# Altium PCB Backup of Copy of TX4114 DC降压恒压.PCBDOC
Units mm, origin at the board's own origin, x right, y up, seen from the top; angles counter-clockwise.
Board outline 84.26 x 72.93 mm, 3 copper layers (TopLayer, MidLayer5, BottomLayer); 15 components, 21 nets, 57 pads, 0 vias.
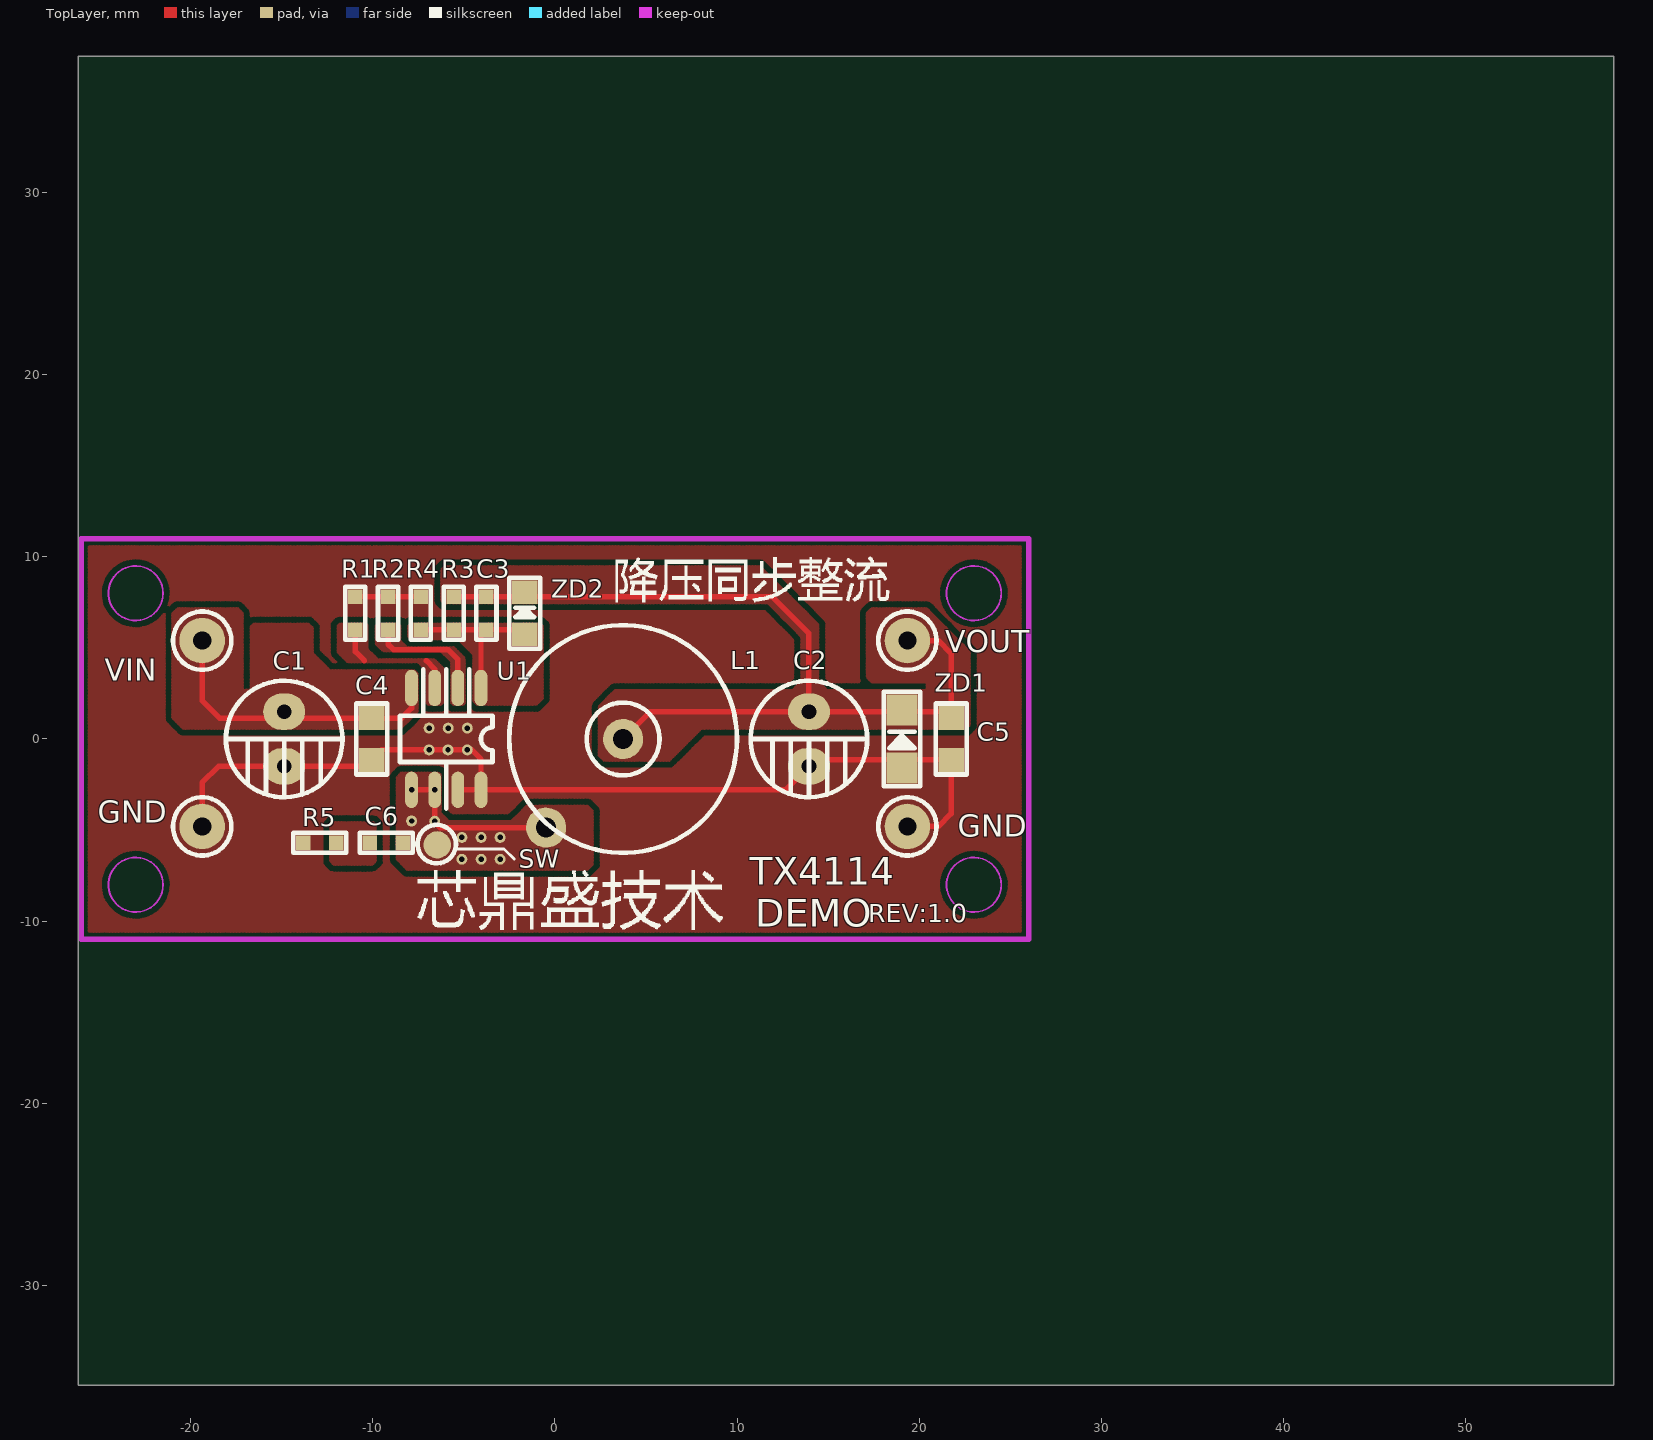
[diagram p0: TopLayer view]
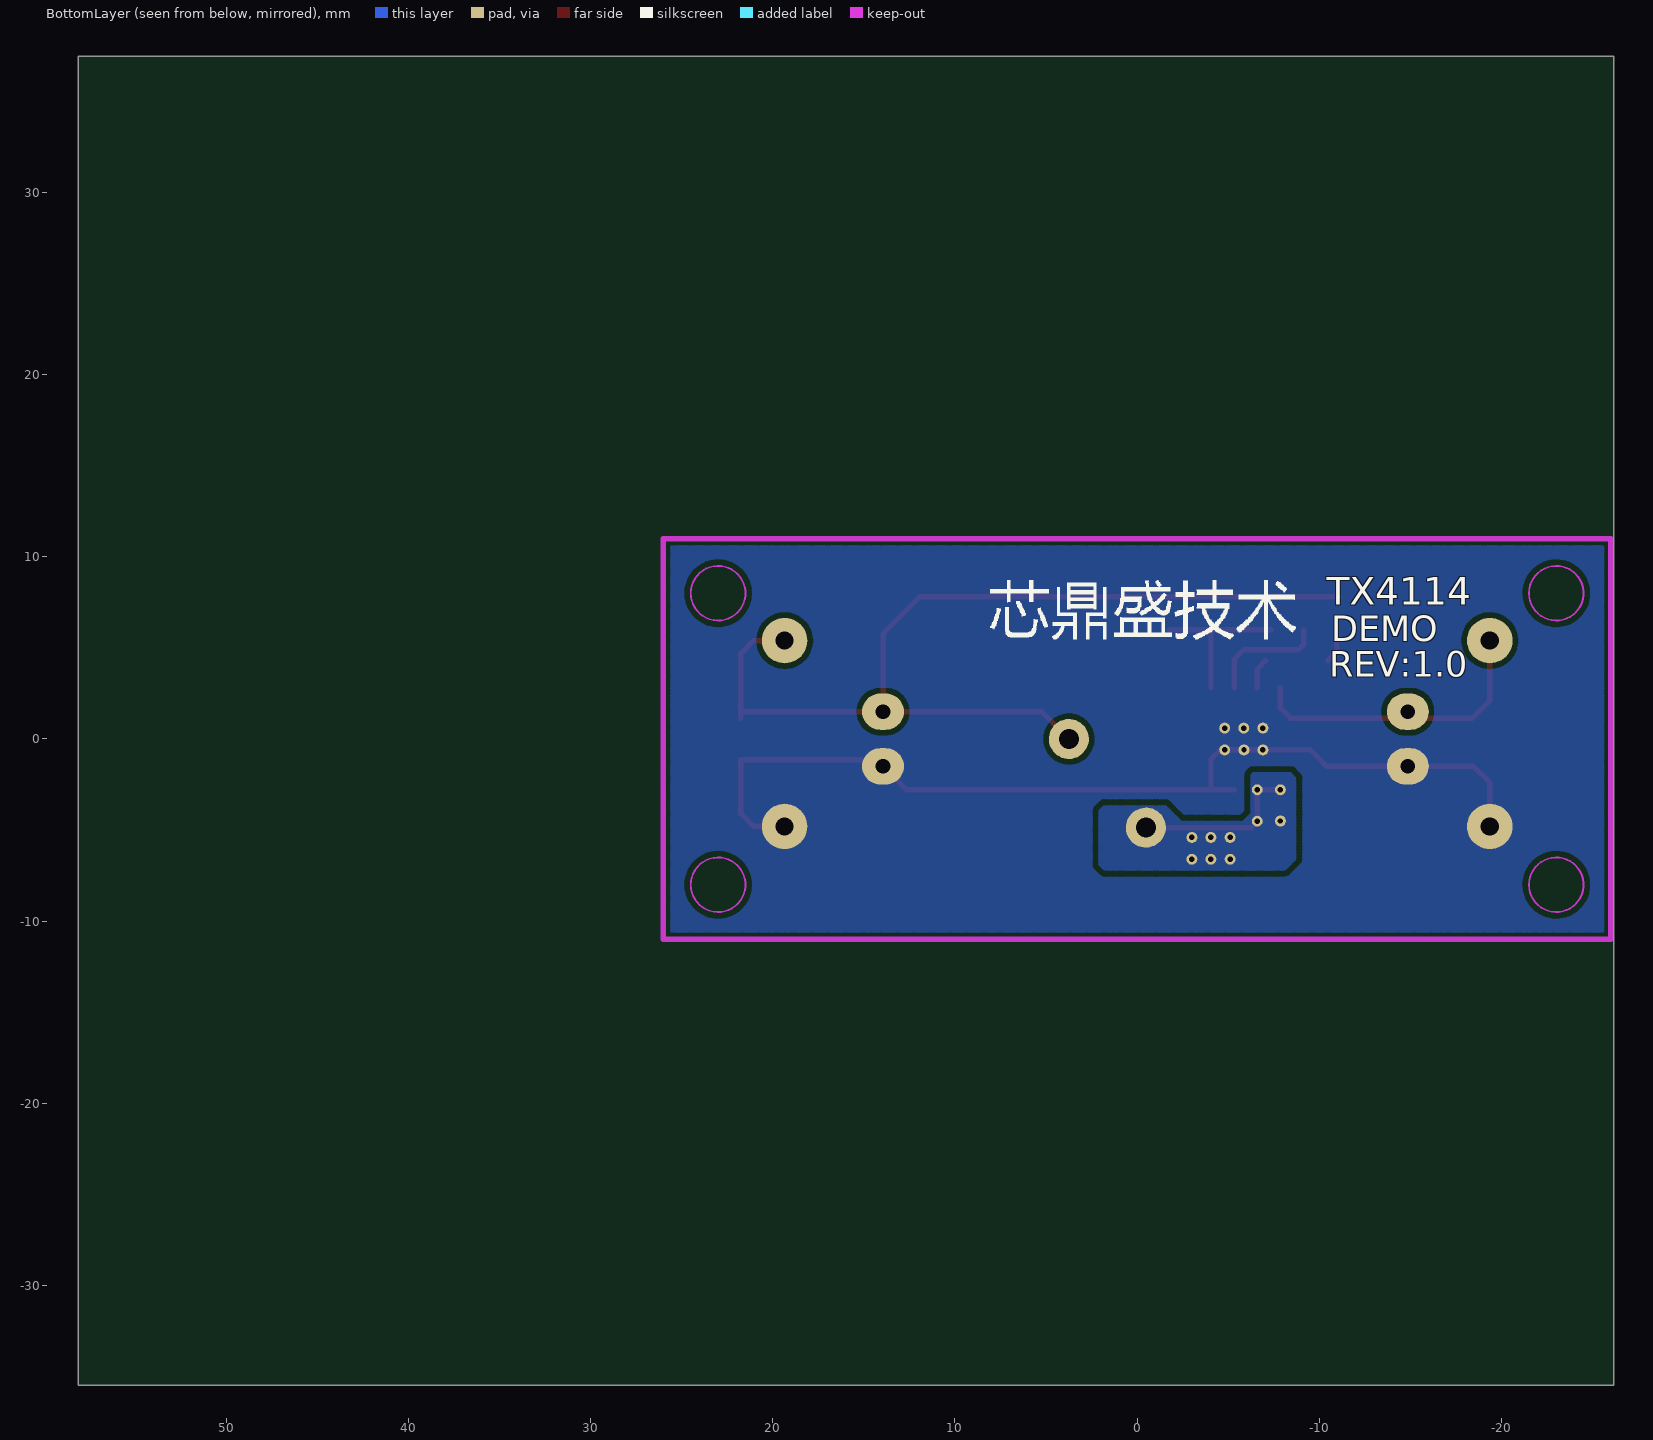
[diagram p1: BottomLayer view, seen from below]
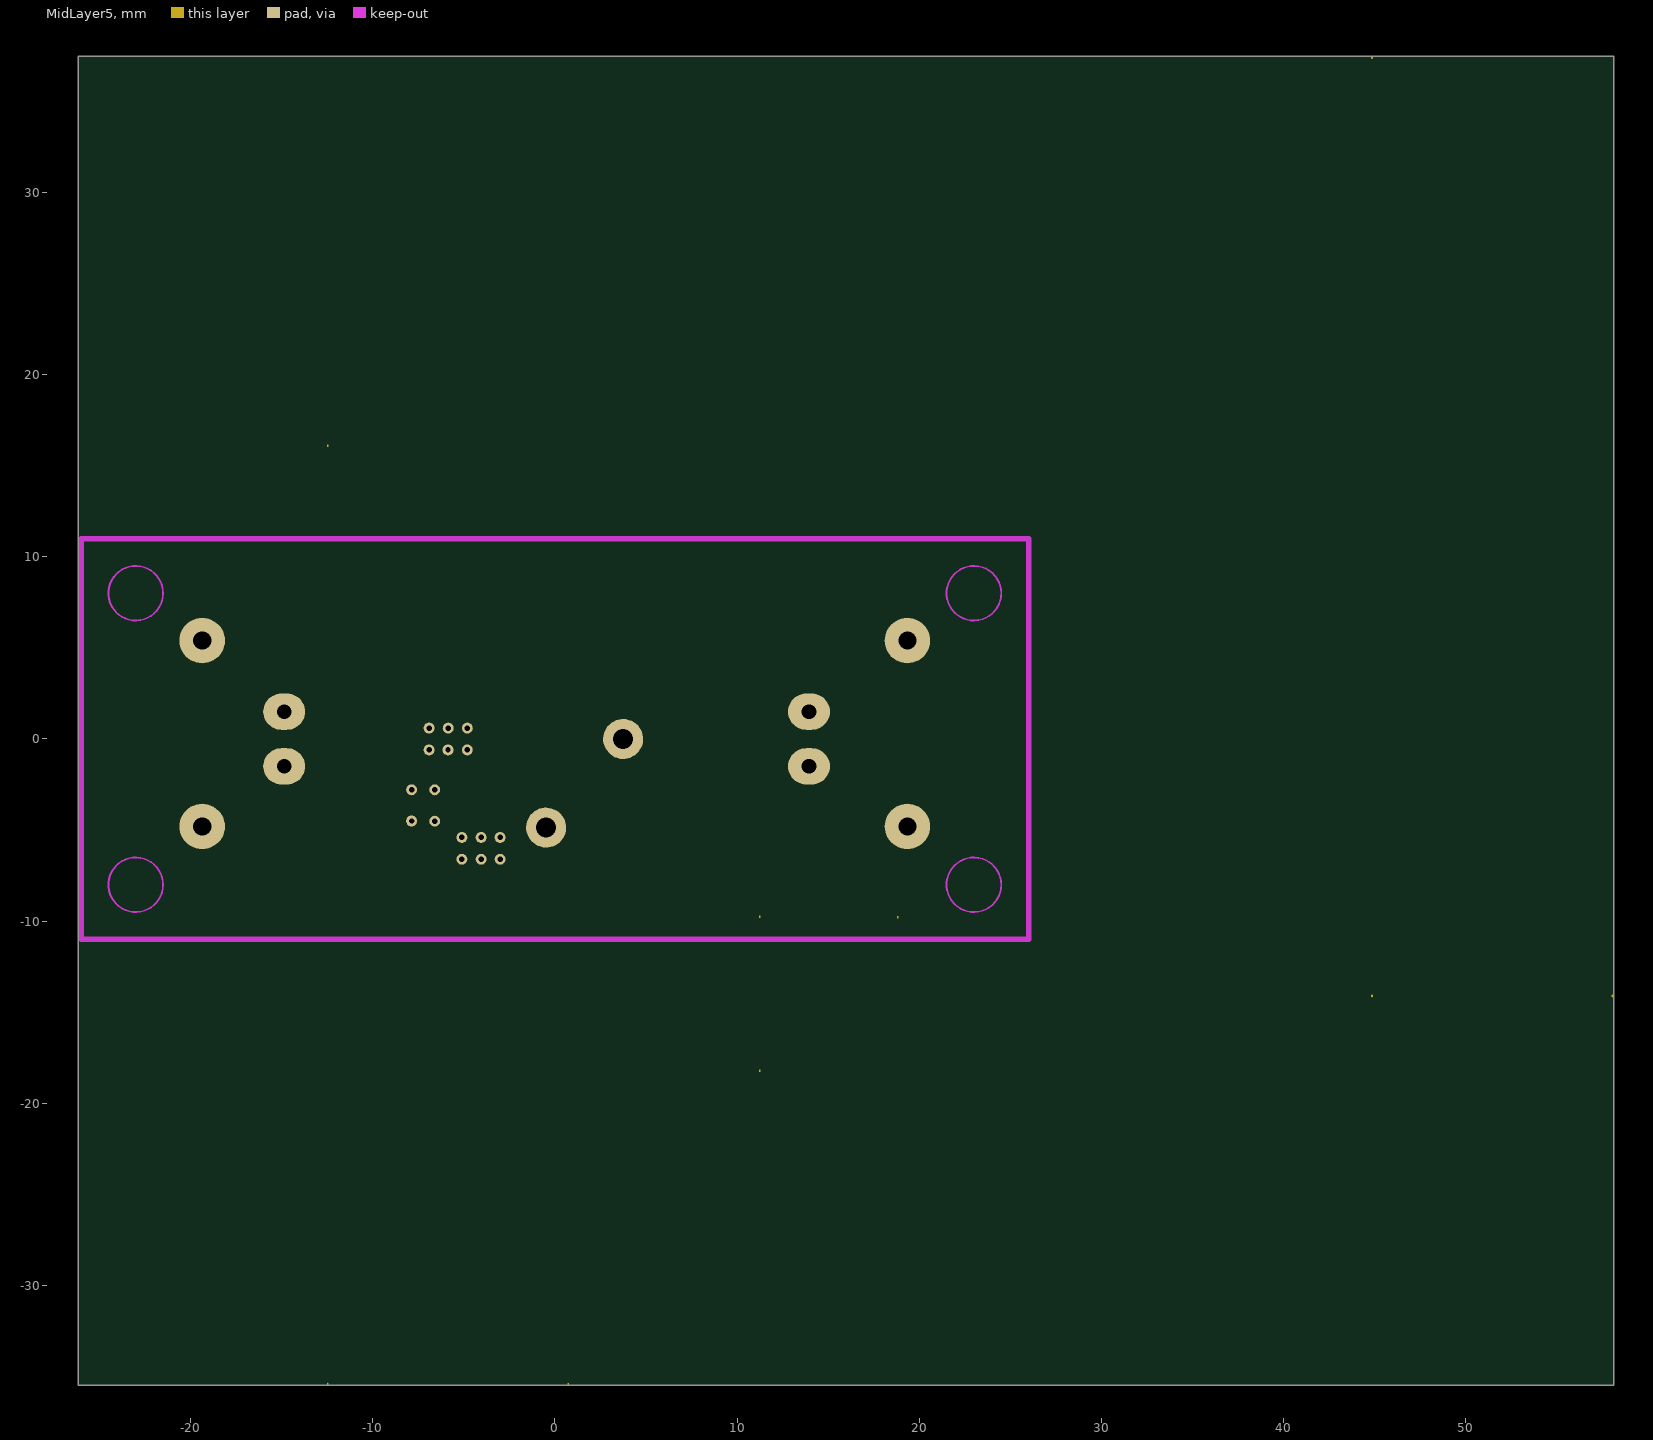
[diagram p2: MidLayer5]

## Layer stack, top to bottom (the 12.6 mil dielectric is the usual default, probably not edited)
TopLayer: signal copper 0.0356
Dielectric: dielectric 0.32, FR-4, Dk 4.8
MidLayer5: signal copper 0.0356
Dielectric: dielectric 0.32, FR-4, Dk 4.8
BottomLayer: signal copper 0.0356

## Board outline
-26.15,-35.464 58.113,-35.464 58.113,37.467 -26.15,37.467

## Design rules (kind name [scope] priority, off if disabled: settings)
Clearance [All] p1: gap=0.3
PlaneConnect [All] p1: planeconnectstyle=Direct reliefexpansion=0.508 reliefentries=4 reliefconductorwidth=0.254 reliefairgap=0.254
PolygonConnect [All] p1: connectstyle=Direct reliefconductorwidth=0.254 reliefentries=4 polygonreliefangle="90 Angle"
RoutingLayers [All] p1: top layer_v5=TRUE mid layer 5_v5=FALSE bottom layer_v5=TRUE
RoutingVias [All] p1: holewidth=0.711 width=1.27 viastyle="Through Hole" minholewidth=0.711 minwidth=1.27 maxholewidth=0.711 maxwidth=1.27
SilkscreenOverComponentPads [All] p1: minsilkscreentomaskgap=0.254
SolderMaskExpansion [All] p1: expansion=0.102
TestPointUsage [All] p1: valid=0 allowmultiple=FALSE
Testpoint [All] p1: side=15 testpointundercomponent=TRUE minsize=1.016 maxsize=2.54 preferedsize=1.524 minholesize=0.508 maxholesize=1.016 preferedholesize=0.813 testpointgrid=0.025 style=1023 order=0123456789
Width [All] p1: maxlimit=0.3 minlimit=0.3 preferedwidth=0.3
21 further rules are at their usual default settings.

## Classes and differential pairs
component class HX1304B: C1 C3 C4 C6 F1 L1 R1 R2 R3 U1

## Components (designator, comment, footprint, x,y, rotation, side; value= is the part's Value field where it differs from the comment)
C1 "100UF/35V" RB-5 -14.85,0 r270 top
C2 "470UF/10V" RB-5 13.95,0 r270 top
C3 "200PF" 0603 -3.75,6.9 r270 top
C4 "104" 0805 -10.05,0 r270 top
C5 "104" 0805 21.75,0 r270 top
C6 "472" 0603 -9.25,-5.7 r0 top
L1 "47UH  44125" L47UH/11.2 3.75,0 r358 top
R1 "68K" 0603 -10.95,6.9 r270 top
R2 "150K" 0603 -9.15,6.9 r270 top
R3 "220K" 0603 -5.55,6.9 r90 top
R4 "68K" 0603 -7.35,6.9 r90 top
R5 "10R" 0603 -12.9,-5.7 r180 top
U1 "TX4114" SO-8 -4.05,2.8 r270 top
ZD1 "6V8" 1206D 19.05,0 r90 top
ZD2 "6V2" 0805D -1.65,6.9 r90 top

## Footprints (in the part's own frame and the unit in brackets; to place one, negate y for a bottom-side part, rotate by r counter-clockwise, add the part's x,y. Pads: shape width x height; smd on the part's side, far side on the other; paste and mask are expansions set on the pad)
0603 [mm]
  rect 0.8x0.8 smd: 1(-0.9,0) 2(0.9,0)
  silkscreen extent -1.45,-0.55 1.45,0.55
0805 [mm]
  rect 1.3x1.4 smd: 1(-1.15,0) 2(1.15,0)
  silkscreen extent -1.95,-0.85 1.95,0.85
0805D [mm]
  rect 1.3x1.4 smd: 1(-1.15,0) 2(1.15,0)
  silkscreen extent -1.95,-0.85 1.95,0.85
1206D [mm]
  rect 1.7x1.7 smd: 1(-1.6,0) 2(1.6,0)
  silkscreen extent -2.6,-1 2.6,1
L47UH/11.2 [mm]
  round 2.2 hole 1.1: 1(-4.051,-5.003) 2(0,0)
  silkscreen extent -6.25,-6.25 6.25,6.25
RB-5 [mm]
  oval 2x2.3 hole 0.8: 1(-1.5,0) 2(1.5,0)
  silkscreen extent -3.2,-3.2 3.2,3.2
SO-8 [mm]
  oval 2x0.7 smd: 1(0,0) 2(0,-1.27) 3(0,-2.54) 4(0,-3.81) 5(5.588,-3.81) 6(5.588,-2.54) 7(5.588,-1.27) 8(5.588,0)
  silkscreen extent -1.03,-4.45 6.61,0.63

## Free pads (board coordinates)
  round 2.5 hole 1: 0(-19.35,5.4) 1(-19.35,-4.8) 2(19.35,5.4) 3(19.35,-4.8)
  round 1.5 smd: 1(-6.45,-5.81)
  round 0.6 hole 0.3: 5(-6.9,0.6) 6(-5.85,0.6) 7(-4.8,0.6) 8(-4.8,-0.6) 9(-5.86,-0.6) 10(-6.9,-0.6) 11(-5.1,-5.4) 12(-4.04,-5.4) 13(-3,-5.4) 14(-5.1,-6.6) 15(-4.04,-6.6) 16(-3,-6.6) 17(-7.86,-2.788) 18(-6.59,-2.788) 19(-7.86,-4.5) 20(-6.59,-4.51)

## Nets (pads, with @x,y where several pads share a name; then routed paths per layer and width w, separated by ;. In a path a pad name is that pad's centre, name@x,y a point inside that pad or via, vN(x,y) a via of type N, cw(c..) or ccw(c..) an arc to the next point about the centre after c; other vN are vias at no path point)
1: C6.1 R5.1
2: 
5: 
6: 
7: 
8: 
EN: 
FB: C3.2 R3.1 R4.1 U1.1 ZD2.1 | length 8.8
  TopLayer w0.3: R4.1 R3.1 C3.2@-4.05,6 ; U1.1 C3.2@-4.05,6 ; ZD2.1@-1.75,6 C3.2 C3.2@-4.05,6
GND: C1.2 C2.2 C4.2 C5.2 pad.1@-19.35,-4.8 pad.3 pad.5 pad.6 pad.7 pad.8 pad.9 pad.10 R1.1 R2.1 R4.2 R5.2 U1.7 U1.8 ZD1.1 | length 57.4
  TopLayer w0.3: pad.1@-19.35,-4.8 -19.35,-2.4 -18.45,-1.5 C1.2 -10.4,-1.5 C4.2 -9.5,-0.6 pad.10 pad.9 pad.8 -4.55,-0.6 -4.05,-1.1 U1.8 ; R1.1@-11.05,7.8 R1.1 R2.1 R4.2 ; U1.7 U1.8 ; pad.3 21.05,-4.8 21.75,-4.1 C5.2 19.05,-1.15 14.3,-1.15 C2.2 12.662,-2.788 U1.8
ILIM: R1.2 U1.3 | length 3.6
  TopLayer w0.3: R1.2 -10.95,4.8 -10.45,4.3 ; -7.05,4.3 -6.59,3.84 U1.3
NetF1_2: 
NetR1_2: 
NetR2_2: 
NetR3_2: 
NetU1_1: 
NetU1_6: 
RT: R2.2 U1.2 | length 6.5
  TopLayer w0.3: R2.2 -9.15,5.2 -8.85,4.9 -5.85,4.9 -5.32,4.37 U1.2
SW: C6.2 L1.1 pad.1@-6.45,-5.81 pad.11 pad.12 pad.13 pad.14 pad.15 pad.16 pad.17 pad.18 pad.19 pad.20 U1.5 U1.6 | length 9.3
  TopLayer w0.3: U1.5 U1.6 pad.20 -6.59,-4.56 -6.292,-4.858 L1.1
VCC: C1.1 C4.1 pad.0 U1.4 | length 16.5
  TopLayer w0.3: pad.0 -19.35,2.1 -18.4,1.15 -14.85,1.15 C4.1 -8.4,1.15 -7.86,1.69 U1.4
VIN: 
VOUT: C2.1 C3.1 C5.1 L1.2 pad.2 R3.2 ZD1.2 ZD2.2 | length 49.3
  TopLayer w0.3: R3.2 11.95,7.8 13.95,5.8 C2.1 ; L1.2 5.25,1.5 C5.1@21.55,1.5 ; pad.2 21.05,5.4 21.75,4.7 C5.1
copper on no net: | length 2.2
  MidLayer5 w0.064: -12.428,-35.4 ccw(c-12.46,-35.4) -12.428,-35.4 ; -12.428,-35.4 ccw(c-12.46,-35.4) -12.428,-35.4 ; 44.882,-14.1 ccw(c44.85,-14.1) 44.882,-14.1 ; 44.882,-14.1 ccw(c44.85,-14.1) 44.882,-14.1 ; -12.428,16.103 ccw(c-12.46,16.103) -12.428,16.103 ; 0.772,-35.4 ccw(c0.74,-35.4) 0.772,-35.4 ; 11.283,-18.209 ccw(c11.251,-18.209) 11.283,-18.209 ; 11.283,-9.747 ccw(c11.251,-9.747) 11.283,-9.747 ; 18.861,-9.782 ccw(c18.829,-9.782) 18.861,-9.782 ; 44.882,37.403 ccw(c44.85,37.403) 44.882,37.403 ; 58.082,-14.1 ccw(c58.05,-14.1) 58.082,-14.1

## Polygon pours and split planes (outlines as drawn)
FB on TopLayer "TopLayer-FB" (hatched 90Degree grid 0.08 track 0.1, remove dead copper, pour order 1000): -4.5,3 -4.5,4.64 -5.31,5.45 -7.88,5.45 -8.05,5.62 -8.05,6.22 -7.92,6.35 -0.78,6.35 -0.64,6.21 -0.64,2.23 -1.02,1.85 -4.25,1.85 -4.5,2.1
RT on TopLayer "TopLayer-RT" (hatched 90Degree grid 0.08 track 0.1, remove dead copper, pour order 1001): -4.92,2.44 -4.92,4.43 -5.53,5.04 -8.1,5.04 -8.45,5.39 -8.45,6.23 -8.57,6.35 -9.71,6.35 -9.84,6.22 -9.84,5.21 -9.43,4.8 -6.26,4.8 -5.7,4.24 -5.7,1.98 -5.57,1.85 -5.02,1.85 -4.92,1.95 -4.92,2.43
ILIM on TopLayer "TopLayer-ILIM" (hatched 90Degree grid 0.08 track 0.1, remove dead copper, pour order 1002): -6.11,2.1 -6.11,3.9 -6.61,4.4 -9.72,4.4 -10.26,4.94 -10.26,6.25 -10.36,6.35 -11.81,6.35 -11.94,6.22 -11.94,4.76 -11.38,4.2 -7.5,4.2 -7.07,3.77 -7.07,1.99 -6.93,1.85 -6.26,1.85 -6.11,2
VCC on TopLayer "TopLayer-VCC" (hatched 90Degree grid 0.08 track 0.1, remove dead copper, pour order 1003): -7.5,3.3 -7.5,1.5 -8.45,0.55 -20.4,0.55 -21,1.15 -21,6.9 -20.7,7.2 -17.4,7.2 -17.1,6.9 -17.1,2.71 -16.7,2.71 -16.7,6.17 -16.52,6.35 -13.5,6.35 -13.26,6.11 -13.26,4.72 -12.34,3.8 -7.71,3.8 -7.5,3.59
SW on TopLayer "TopLayer-SW" (hatched 90Degree grid 0.08 track 0.1, remove dead copper, pour order 1004): -6.24,-2.41 -6.24,-4.07 -5.81,-4.5 -2.4,-4.5 -1.55,-3.65 1.81,-3.65 2.1,-3.94 2.1,-6.9 1.8,-7.2 -8.1,-7.2 -8.7,-6.6 -8.7,-2.1 -8.44,-1.84 -6.36,-1.84 -6.24,-1.96
VOUT on TopLayer "TopLayer-VOUT" (hatched 90Degree grid 0.08 track 0.1, remove dead copper, pour order 1005): 2.4,-0.3 2.4,1.8 3.3,2.7 20.4,2.7 20.4,3.09 17.4,3.09 17.1,3.39 17.1,6.9 17.4,7.2 20.4,7.2 22.8,4.8 22.8,0.74 22.61,0.55 8.05,0.55 6.29,-1.21 2.7,-1.21 2.4,-0.91
1 on TopLayer "TopLayer-1" (hatched 90Degree grid 0.08 track 0.1, remove dead copper, pour order 1006): -11.4,-6.91 -12.15,-6.91 -12.35,-6.71 -12.35,-4.72 -12.19,-4.56 -9.94,-4.56 -9.8,-4.7 -9.8,-6.71 -10,-6.91
GND on TopLayer "TopLayer-GND" (hatched 90Degree grid 0.08 track 0.1, remove dead copper, pour order 1007): -26,-11 26,-11 26,10.98 -26,10.98
VOUT on TopLayer "TopLayer-VOUT 1" (hatched 90Degree grid 0.08 track 0.1, remove dead copper, pour order 1008): 12.6,2.699 13.03,2.699 13.5,3.169 13.5,5.62 11.68,7.44 -6.08,7.44 -6.24,7.6 -6.24,9.31 -6.06,9.49 11.28,9.49 14.49,6.28 14.49,3.16 14.95,2.7 15.409,2.7 15.409,2.379 12.6,2.379
GND on BottomLayer "BottomLayer-GND" (hatched 90Degree grid 0.08 track 0.1, remove dead copper, pour order 1009): -25.99,10.99 25.97,10.99 25.97,-11.02 -25.92,-11.02 -25.92,11.15
SW on BottomLayer "BottomLayer-SW" (hatched 90Degree grid 0.08 track 0.1, remove dead copper, pour order 1010): 2.09,-4.27 2.09,-3.94 1.81,-3.66 -1.55,-3.66 -2.4,-4.51 -5.83,-4.51 -6.24,-4.1 -6.24,-1.97 -6.36,-1.85 -8.42,-1.85 -8.7,-2.13 -8.7,-6.59 -8.1,-7.19 1.8,-7.19 2.09,-6.9
GND on MultiLayer (hatched 90Degree grid 0.08 track 0.1, remove dead copper): -20.26,-478.9

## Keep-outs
KeepOutLayer:
  circle w0.1: c-23,-8 r1.5
  circle w0.1: c-23,8 r1.5
  circle w0.1: c23,-8 r1.5
  circle w0.1: c23,8 r1.5
  lines w0.3: -26,-11 26,-11 26,11 -26,11 -26,-11

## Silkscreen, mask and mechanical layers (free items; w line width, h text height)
TopOverlay:
  drawing of 2418 lines, arcs and shapes, not listed
  text "VOUT" at 21.44,4.75 h1.2
  text "VIN" at -24.69,3.19 h1.2
  text "GND" at -25.09,-4.6 h1.2
  text "GND" at 22.12,-5.36 h1.2
  text "SW" at -1.99,-7.06 h1
  text "TX4114" at 10.71,-7.99 h1.5
  text "REV:1.0" at 17.19,-10.06 h1
  text "DEMO" at 10.99,-10.31 h1.52
BottomOverlay:
  drawing of 1289 lines, arcs and shapes, not listed
  text "TX4114" at -10.39,7.37 h1.5
  text "DEMO" at -10.65,5.37 h1.4
  text "REV:1.0" at -10.55,3.42 h1.4
TopSolder:
  rectangle: 9.91,-5.839 12.11,-3.25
